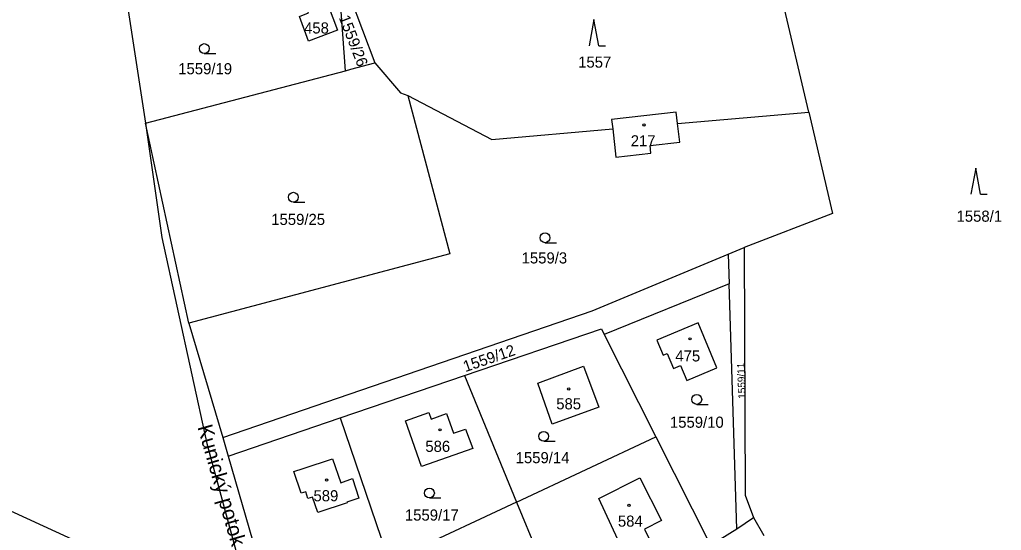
# Model space of a CAD drawing. Extents: x -725728 to -720881, y -1068679 to -1063504.
# Drawn here: x -723744.1 to -723594.1, y -1066698.7 to -1066620.7 of the extents above; entities that cross this region are included whole.
import ezdxf

# ---------------------------------------------------------------- set-up
doc = ezdxf.new("R2010")
doc.units = 0
for name, color, linetype in [('Hranice parcel', 7, 'Continuous'), ('Parcelní čísla', 7, 'Continuous'), ('Pop  PČ popisy', 7, 'Continuous'), ('Značky budov', 7, 'Continuous'), ('Značky kultur', 7, 'Continuous')]:
    doc.layers.add(name, color=color, linetype=linetype)

# ---------------------------------------------------------------- blocks, each defined once
blk = doc.blocks.new('4.02_3')
at = {"layer": 'Značky budov'}
blk.add_circle((-0.001, 0), 0.0175, dxfattribs=at)
blk = doc.blocks.new('4.02_4')
at = {"layer": 'Značky budov'}
blk.add_circle((-0.001, 0), 0.0175, dxfattribs=at)
blk = doc.blocks.new('3.04_2')
at = {"layer": 'Značky kultur'}
blk.add_line((0.001, 0), (0.176, 0), dxfattribs=at)
blk.add_circle((0.001, 0.075), 0.075, dxfattribs=at)
blk = doc.blocks.new('3.08_2')
at = {"layer": 'Značky kultur'}
for p, q in [((0, 0.4), (-0.075, 0)), ((0.075, 0), (0, 0.4)), ((0.075, 0), (0.175, 0))]:
    blk.add_line(p, q, dxfattribs=at)
blk = doc.blocks.new('3.08_1')
at = {"layer": 'Značky kultur'}
for p, q in [((0, 0.4), (-0.075, 0)), ((0.075, 0), (0, 0.4)), ((0.075, 0), (0.175, 0))]:
    blk.add_line(p, q, dxfattribs=at)

msp = doc.modelspace()

# ---------------------------------------------------------------- linework, layer by layer
at = {"layer": 'Hranice parcel'}
for p, q in [((-723694.3, -1066628.46), (-723695.45, -1066612.24)), ((-723695.45, -1066612.24), (-723689.78, -1066627.27)), ((-723623.5, -1066634.8), (-723628.72, -1066612.51)), ((-723727.58, -1066618.58), (-723724.86, -1066636.46)), ((-723724.86, -1066636.46), (-723694.3, -1066628.46)), ((-723643.57, -1066636.52), (-723623.5, -1066634.8)), ((-723718.22, -1066667.04), (-723724.86, -1066636.46)), ((-723724.86, -1066636.46), (-723722.35, -1066653.98)), ((-723635.79, -1066656.51), (-723633.35, -1066655.49)), ((-723635.79, -1066656.51), (-723635.65, -1066661.03)), ((-723635.65, -1066661.03), (-723654.74, -1066668.79)), ((-723634.5, -1066698.47), (-723635.65, -1066661.03)), ((-723722.66, -1066706.21), (-723819.02, -1066662.15)), ((-723718.22, -1066667.04), (-723713.02, -1066684.51)), ((-723654.74, -1066668.79), (-723646.85, -1066684.45)), ((-723695.09, -1066681.54), (-723676.12, -1066675.06)), ((-723676.12, -1066675.06), (-723668.17, -1066694.41)), ((-723712.19, -1066687.39), (-723695.09, -1066681.54)), ((-723695.09, -1066681.54), (-723687.58, -1066703.48)), ((-723713.02, -1066684.51), (-723712.19, -1066687.39)), ((-723668.17, -1066694.41), (-723646.85, -1066684.45)), ((-723646.85, -1066684.45), (-723638.51, -1066701)), ((-723712.19, -1066687.39), (-723705.16, -1066711.69)), ((-723668.17, -1066694.41), (-723687.58, -1066703.48)), ((-723668.17, -1066694.41), (-723660.36, -1066713)), ((-723634.5, -1066698.47), (-723631.92, -1066696.75)), ((-723631.92, -1066696.75), (-723630.37, -1066699.51)), ((-723638.51, -1066701), (-723634.5, -1066698.47))]:
    msp.add_line(p, q, dxfattribs=at)
for points in [[(-723701.33, -1066620.18), (-723699.95, -1066619.61), (-723701.37, -1066615.81), (-723698.37, -1066614.69), (-723695.52, -1066622.29), (-723699.92, -1066623.94), (-723701.33, -1066620.18)], [(-723694.3, -1066628.46), (-723693.44, -1066628.23), (-723689.78, -1066627.27)], [(-723689.78, -1066627.27), (-723685.86, -1066631.84), (-723684.76, -1066632.25)], [(-723684.76, -1066632.25), (-723678.34, -1066656.48), (-723718.22, -1066667.04)], [(-723684.76, -1066632.25), (-723671.92, -1066638.96), (-723653.46, -1066637.37)], [(-723643.57, -1066636.52), (-723643.78, -1066634.82), (-723653.62, -1066635.92), (-723653.46, -1066637.37)], [(-723623.5, -1066634.8), (-723619.87, -1066650.31), (-723633.35, -1066655.49)], [(-723653.46, -1066637.37), (-723652.98, -1066641.68), (-723647.61, -1066641.09), (-723647.74, -1066639.89), (-723643.22, -1066639.39), (-723643.57, -1066636.52)], [(-723722.35, -1066653.98), (-723715.44, -1066685.43), (-723710.51, -1066703.68)], [(-723713.02, -1066684.51), (-723656.57, -1066665.16), (-723635.79, -1066656.51)], [(-723633.35, -1066655.49), (-723633.22, -1066693.33), (-723631.92, -1066696.75)], [(-723642.14, -1066675.83), (-723637.56, -1066673.86), (-723640.42, -1066667.01), (-723646.72, -1066669.64), (-723645.74, -1066671.95), (-723645.14, -1066671.7), (-723644.18, -1066673.97), (-723643.12, -1066673.52), (-723642.14, -1066675.83)], [(-723676.12, -1066675.06), (-723655.19, -1066667.9), (-723654.74, -1066668.79)], [(-723657.91, -1066673.63), (-723655.58, -1066679.87), (-723662.68, -1066682.51), (-723664.91, -1066676.23), (-723657.91, -1066673.63)], [(-723682.67, -1066688.98), (-723685.13, -1066681.98), (-723681.56, -1066680.72), (-723681.21, -1066681.72), (-723678.83, -1066680.88), (-723677.77, -1066683.88), (-723675.96, -1066683.25), (-723674.81, -1066686.21), (-723682.67, -1066688.98)], [(-723694.07, -1066694.41), (-723694.03, -1066694.54), (-723698.53, -1066695.98), (-723699.31, -1066693.63), (-723700.02, -1066693.87), (-723700.36, -1066692.82), (-723701.05, -1066693.05), (-723702.15, -1066689.74), (-723700.74, -1066689.27), (-723696.26, -1066687.79), (-723695, -1066691.47), (-723693.21, -1066690.8), (-723692.22, -1066693.8), (-723694.07, -1066694.41)], [(-723655.56, -1066693.83), (-723649.32, -1066690.69), (-723646.02, -1066697.23), (-723648.62, -1066698.54), (-723647.77, -1066700.21), (-723651.69, -1066702.19), (-723655.56, -1066693.83)]]:
    msp.add_lwpolyline(points, dxfattribs=at)

# ---------------------------------------------------------------- block references
at = {"layer": 'Značky budov', "xscale": 10, "yscale": 10}
for name, p in [('4.02_3', (-723648.67, -1066636.75)), ('4.02_3', (-723641.63, -1066669.45)), ('4.02_3', (-723660.17, -1066677.11)), ('4.02_3', (-723679.81, -1066683.36)), ('4.02_3', (-723697.15, -1066691.03)), ('4.02_4', (-723650.96, -1066694.89))]:
    msp.add_blockref(name, p, dxfattribs=at)
at = {"layer": 'Značky kultur', "xscale": 10, "yscale": 10}
for name, p in [('3.08_2', (-723656.32, -1066624.66)), ('3.04_2', (-723715.87, -1066625.83)), ('3.08_1', (-723597.99, -1066647.34)), ('3.04_2', (-723702.25, -1066648.55)), ('3.04_2', (-723663.8, -1066654.75)), ('3.04_2', (-723640.62, -1066679.46)), ('3.04_2', (-723664, -1066685.09)), ('3.04_2', (-723681.46, -1066693.77))]:
    msp.add_blockref(name, p, dxfattribs=at)

# ---------------------------------------------------------------- texts
at = {"layer": 'Parcelní čísla'}
for s, height, rotation, p in [('1559/26', 1.7, 291, (-723695.32, -1066620.34)), ('1559/12', 1.7, 19, (-723675.96, -1066674.55)), ('1559/11', 1.14, 92, (-723633.13, -1066678.59))]:
    msp.add_text(s, height=height, rotation=rotation, dxfattribs=at).set_placement(p)
for s, p in [('458', (-723700.61, -1066622.78)), ('1557', (-723658.73, -1066628)), ('1559/19', (-723719.83, -1066629.01)), ('217', (-723650.7, -1066640.03)), ('1559/25', (-723705.62, -1066652.04)), ('1558/1', (-723600.92, -1066651.55)), ('1559/3', (-723667.37, -1066657.93)), ('475', (-723643.88, -1066672.91)), ('585', (-723662.08, -1066680.23)), ('1559/10', (-723644.71, -1066683.04)), ('586', (-723682.08, -1066686.73)), ('1559/14', (-723668.28, -1066688.46)), ('589', (-723699.17, -1066694.28)), ('1559/17', (-723685.2, -1066697.23)), ('584', (-723652.66, -1066698.16))]:
    msp.add_text(s, height=1.7, dxfattribs=at).set_placement(p)
at = {"layer": 'Pop  PČ popisy'}
msp.add_text('Kunický potok', height=2.3, rotation=286, dxfattribs=at).set_placement((-723716.92, -1066682.92))

doc.saveas('drawing.dxf')
